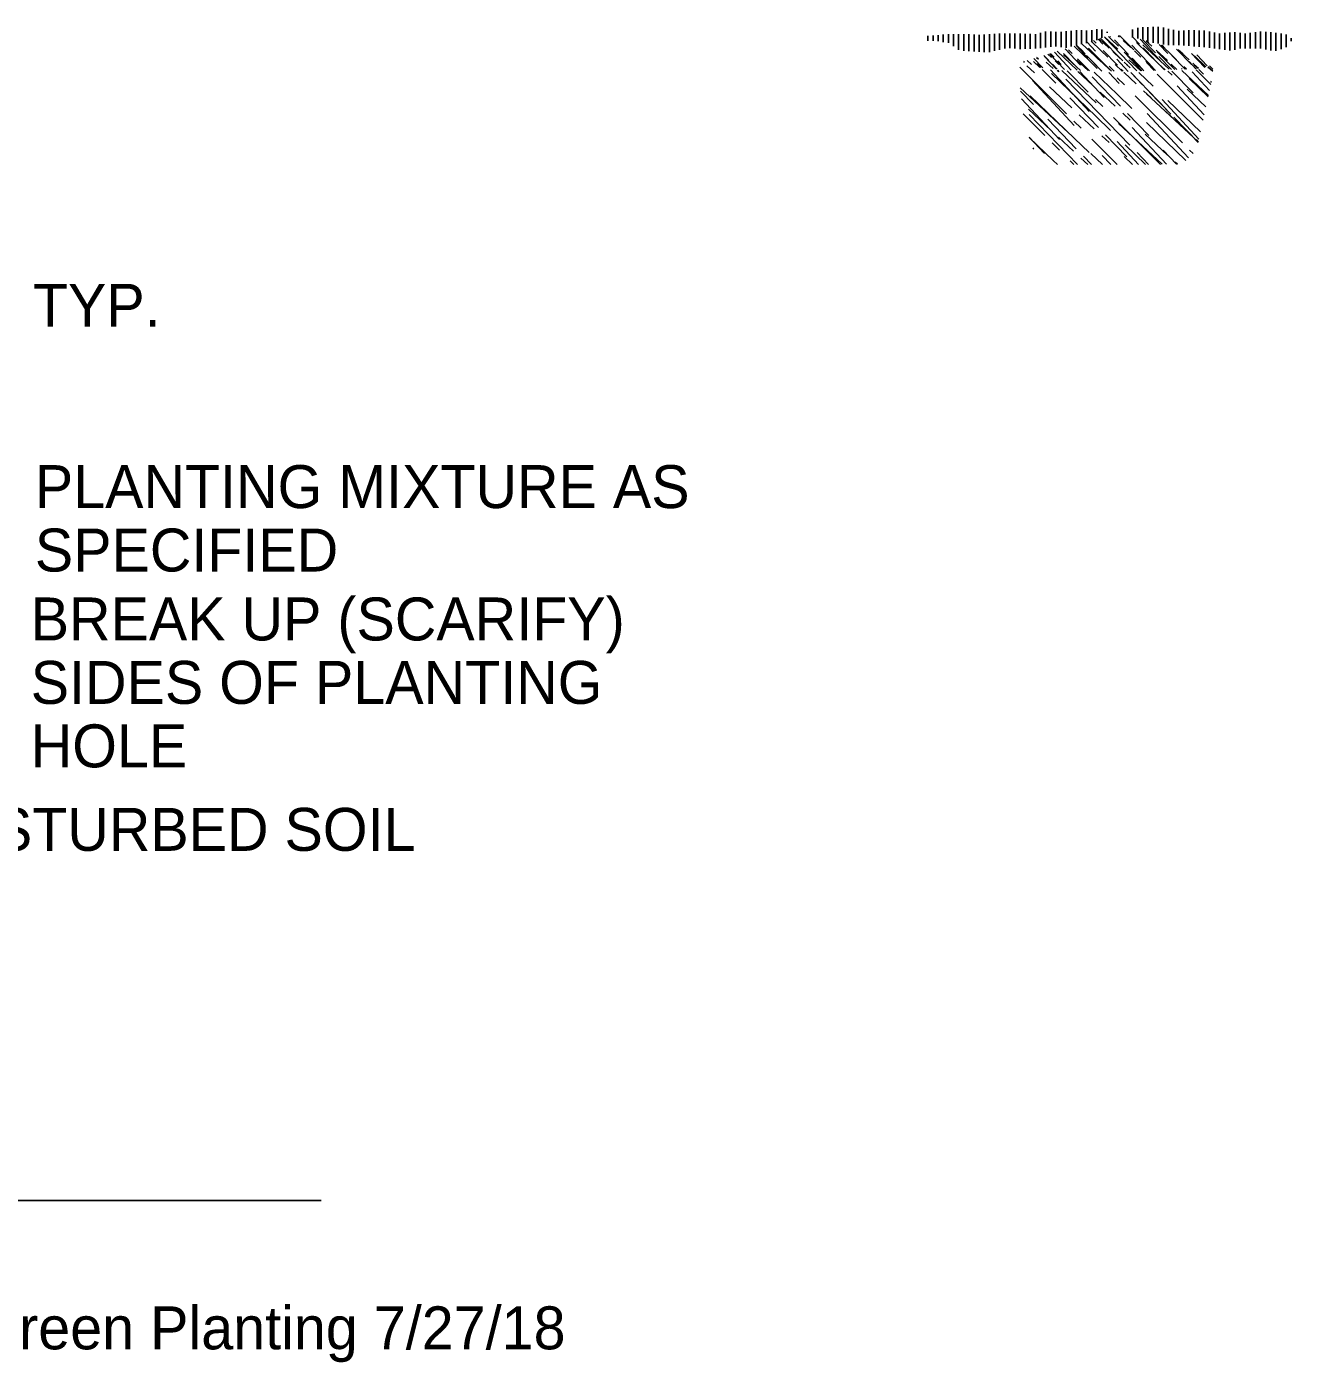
# Model space of a CAD drawing. Extents: x 10082 to 10257, y 10014 to 10069.
# Drawn here: x 10147.66 to 10168.25, y 10014.41 to 10036.16 of the extents above; entities that cross this region are included whole.
import ezdxf

# ---------------------------------------------------------------- set-up
doc = ezdxf.new("R2010")
doc.units = 0
for name, color, linetype in [('Default', 7, 'Continuous'), ('G-ANNO-CELL', 7, 'Continuous'), ('G-ANNO-TEXT', 7, 'Continuous'), ('G-DETL-TEXT', 7, 'Continuous')]:
    doc.layers.add(name, color=color, linetype=linetype)

# ---------------------------------------------------------------- blocks, each defined once
blk = doc.blocks.new('_X3')
at = {"layer": 'Default'}
for p, q in [((2.0243, 1.27594), (2.00019, 1.30005)), ((2.00379, 1.30073), (2.00766, 1.29713)), ((2.01867, 1.29176), (2.01176, 1.29892)), ((2.01595, 1.29868), (2.03605, 1.27712)), ((2.09892, 1.29113), (2.09126, 1.29879)), ((2.09277, 1.29887), (2.09513, 1.29644)), ((2.09741, 1.30026), (2.09986, 1.29797)), ((2.09986, 1.2991), (2.09818, 1.30084)), ((2.00665, 1.29312), (2.02831, 1.2699)), ((2.03941, 1.27469), (2.01657, 1.29675)), ((2.01961, 1.29846), (2.0203, 1.29775)), ((2.0396, 1.28172), (2.02178, 1.29833)), ((2.02398, 1.29394), (2.05706, 1.25968)), ((2.03552, 1.28717), (2.02452, 1.29817)), ((2.03015, 1.29786), (2.03784, 1.29069)), ((2.03121, 1.29782), (2.04379, 1.28434)), ((2.05215, 1.27995), (2.03745, 1.29517)), ((2.05044, 1.28611), (2.0386, 1.29755)), ((2.04621, 1.29726), (2.05153, 1.29156)), ((2.05423, 1.29091), (2.05049, 1.29465)), ((2.05403, 1.2972), (2.05396, 1.29726)), ((2.05407, 1.29726), (2.06028, 1.29147)), ((2.06357, 1.29098), (2.05744, 1.29733)), ((2.05749, 1.29733), (2.07609, 1.27806)), ((2.06908, 1.29018), (2.0616, 1.29741)), ((2.09486, 1.27273), (2.07107, 1.29652)), ((2.07661, 1.29795), (2.07884, 1.29587)), ((2.08969, 1.28678), (2.07879, 1.29807)), ((2.09766, 1.28545), (2.08382, 1.29836)), ((2.09752, 1.28479), (2.08772, 1.29425)), ((2.08918, 1.29773), (2.09823, 1.28803)), ((2.0988, 1.29263), (2.09916, 1.29226)), ((2.02516, 1.26624), (2.00034, 1.28938)), ((2.00726, 1.28073), (2.00053, 1.2877)), ((2.02839, 1.26327), (2.00555, 1.28533)), ((2.0154, 1.28991), (2.02701, 1.27908)), ((2.04171, 1.28708), (2.04945, 1.27986)), ((2.05805, 1.27876), (2.05044, 1.28611)), ((2.08417, 1.26098), (2.05985, 1.2853)), ((2.06415, 1.28787), (2.06802, 1.28426)), ((2.09237, 1.26144), (2.06564, 1.28637)), ((2.07827, 1.27575), (2.06725, 1.28717)), ((2.08144, 1.29051), (2.09547, 1.27547)), ((2.08658, 1.28865), (2.09636, 1.27953)), ((2.00097, 1.2837), (2.02057, 1.26268)), ((2.00457, 1.2783), (2.01619, 1.26747)), ((2.04073, 1.26892), (2.02603, 1.28415)), ((2.04301, 1.27969), (2.03927, 1.28343)), ((2.0737, 1.28329), (2.0927, 1.26292)), ((2.09351, 1.26659), (2.0767, 1.28283)), ((2.01307, 1.26472), (2.00182, 1.27597)), ((2.00495, 1.27556), (2.02992, 1.2497)), ((2.02931, 1.25789), (2.01461, 1.27312)), ((2.03178, 1.26846), (2.02804, 1.2722)), ((2.03088, 1.27547), (2.03862, 1.26825)), ((2.04703, 1.26734), (2.03941, 1.27469)), ((2.07286, 1.24983), (2.04862, 1.27407)), ((2.05332, 1.27626), (2.05719, 1.27265)), ((2.06685, 1.26472), (2.05583, 1.27614)), ((2.08597, 1.2518), (2.06567, 1.27141)), ((2.06596, 1.27608), (2.08736, 1.25313)), ((2.07576, 1.27704), (2.08737, 1.26621)), ((2.07977, 1.27425), (2.09233, 1.26125)), ((2.04249, 1.26465), (2.04636, 1.26104)), ((2.05543, 1.25369), (2.04441, 1.26511)), ((2.07378, 1.24984), (2.05121, 1.27089)), ((2.05822, 1.26886), (2.07596, 1.24984)), ((2.06493, 1.26543), (2.07654, 1.2546)), ((2.09232, 1.2612), (2.08562, 1.26814)), ((2.00496, 1.2639), (2.01283, 1.25547)), ((2.01736, 1.25186), (2.005, 1.26379)), ((2.00731, 1.25782), (2.00686, 1.25828)), ((2.02056, 1.25724), (2.01682, 1.26098)), ((2.02006, 1.26386), (2.0278, 1.25664)), ((2.036, 1.25592), (2.02839, 1.26327)), ((2.05048, 1.24976), (2.0374, 1.26285)), ((2.05048, 1.26164), (2.06153, 1.2498)), ((2.06518, 1.24981), (2.05464, 1.25999)), ((2.08973, 1.25541), (2.08791, 1.25724)), ((2.09124, 1.2626), (2.09239, 1.26153)), ((2.01962, 1.24967), (2.01736, 1.25186)), ((2.0281, 1.24969), (2.02617, 1.25162)), ((2.03167, 1.25304), (2.03522, 1.24972)), ((2.0372, 1.24972), (2.03299, 1.25409)), ((2.04285, 1.24974), (2.03677, 1.25541)), ((2.04274, 1.25442), (2.0471, 1.24975)), ((2.0541, 1.25382), (2.05842, 1.24979)), ((2.06074, 1.25587), (2.06659, 1.24981)), ((2.08121, 1.24986), (2.07421, 1.25711)), ((2.08041, 1.25099), (2.08162, 1.24986))]:
    blk.add_line(p, q, dxfattribs=at)
blk = doc.blocks.new('_X2')
at = {"layer": 'Default'}
for p, q in [((2.05846, 1.31543), (2.05846, 1.31955)), ((2.0611, 1.31488), (2.0611, 1.32049)), ((2.06375, 1.31432), (2.06375, 1.32074)), ((2.0664, 1.31344), (2.0664, 1.32083)), ((2.06904, 1.31275), (2.06904, 1.32091)), ((2.07169, 1.3123), (2.07169, 1.321)), ((2.07433, 1.31186), (2.07433, 1.32052)), ((2.07698, 1.31151), (2.07698, 1.31992)), ((2.07963, 1.31151), (2.07963, 1.31932)), ((2.08227, 1.31151), (2.08227, 1.31896)), ((2.08492, 1.31129), (2.08492, 1.31906)), ((2.08756, 1.31106), (2.08756, 1.31916)), ((2.09021, 1.31083), (2.09021, 1.31926)), ((2.09285, 1.3106), (2.09285, 1.31911)), ((2.0955, 1.31037), (2.0955, 1.31897)), ((2.09815, 1.31014), (2.09815, 1.31856)), ((2.10079, 1.30981), (2.10079, 1.318)), ((2.10344, 1.30946), (2.10344, 1.31754)), ((2.10608, 1.30912), (2.10608, 1.31782)), ((2.10873, 1.30878), (2.10873, 1.3181)), ((2.11138, 1.30911), (2.11138, 1.31811)), ((2.11402, 1.30969), (2.11402, 1.3178)), ((2.11667, 1.30976), (2.11667, 1.31753)), ((2.11931, 1.30976), (2.11931, 1.3179)), ((2.12196, 1.30976), (2.12196, 1.31827)), ((2.1246, 1.30969), (2.1246, 1.31857)), ((2.12725, 1.30919), (2.12725, 1.31841)), ((2.1299, 1.30869), (2.1299, 1.31825)), ((2.13254, 1.3086), (2.13254, 1.31784)), ((2.13519, 1.30938), (2.13519, 1.31743)), ((2.13783, 1.31035), (2.13783, 1.31702)), ((2.14048, 1.31352), (2.14048, 1.31514))]:
    blk.add_line(p, q, dxfattribs=at)
blk = doc.blocks.new('_X1')
at = {"layer": 'Default'}
for p, q in [((2.03994, 1.31413), (2.03994, 1.3197)), ((2.04258, 1.31531), (2.04258, 1.31953)), ((1.95263, 1.31367), (1.95263, 1.31626)), ((1.95527, 1.31367), (1.95527, 1.31649)), ((1.95792, 1.31347), (1.95792, 1.31671)), ((1.96056, 1.31305), (1.96056, 1.31693)), ((1.96321, 1.31262), (1.96321, 1.31716)), ((1.96585, 1.31087), (1.96585, 1.31717)), ((1.9685, 1.30902), (1.9685, 1.31717)), ((1.97115, 1.30856), (1.97115, 1.31717)), ((1.97379, 1.30841), (1.97379, 1.31709)), ((1.97644, 1.30823), (1.97644, 1.31698)), ((1.97908, 1.30803), (1.97908, 1.31687)), ((1.98173, 1.30783), (1.98173, 1.31697)), ((1.98438, 1.30782), (1.98438, 1.31715)), ((1.98702, 1.30847), (1.98702, 1.31734)), ((1.98967, 1.30912), (1.98967, 1.31751)), ((1.99231, 1.30978), (1.99231, 1.31751)), ((1.99496, 1.30997), (1.99496, 1.31751)), ((1.9976, 1.30972), (1.9976, 1.31751)), ((2.00025, 1.30947), (2.00025, 1.31744)), ((2.0029, 1.30951), (2.0029, 1.31735)), ((2.00554, 1.30962), (2.00554, 1.31726)), ((2.00819, 1.30972), (2.00819, 1.31721)), ((2.01083, 1.30997), (2.01083, 1.31787)), ((2.01348, 1.31029), (2.01348, 1.31853)), ((2.01613, 1.31062), (2.01613, 1.31847)), ((2.01877, 1.31073), (2.01877, 1.31833)), ((2.02142, 1.31041), (2.02142, 1.31836)), ((2.02406, 1.31013), (2.02406, 1.31864)), ((2.02671, 1.31079), (2.02671, 1.31892)), ((2.02935, 1.31146), (2.02935, 1.3192)), ((2.032, 1.31203), (2.032, 1.31914)), ((2.03465, 1.31248), (2.03465, 1.31899)), ((2.03729, 1.31294), (2.03729, 1.3192)), ((2.04523, 1.31784), (2.04523, 1.31835))]:
    blk.add_line(p, q, dxfattribs=at)
blk = doc.blocks.new('_X0')
at = {"layer": 'Default'}
for p, q in [((0.62626, 0.34419), (0.62488, 0.34553)), ((0.62556, 0.34559), (0.62589, 0.34524)), ((0.62998, 0.346), (0.63065, 0.34537)), ((0.63797, 0.33863), (0.63055, 0.34605)), ((0.60261, 0.33916), (0.61041, 0.33081)), ((0.6028, 0.33878), (0.60474, 0.33697)), ((0.60617, 0.33676), (0.6043, 0.33863)), ((0.61524, 0.33277), (0.60719, 0.34054)), ((0.60826, 0.34086), (0.61428, 0.33441)), ((0.61286, 0.33657), (0.60862, 0.34097)), ((0.60864, 0.34098), (0.61177, 0.33773)), ((0.62251, 0.3312), (0.6112, 0.34175)), ((0.61391, 0.34257), (0.61815, 0.33802)), ((0.61402, 0.33917), (0.61983, 0.33376)), ((0.62651, 0.32764), (0.61459, 0.33957)), ((0.62075, 0.33848), (0.6159, 0.34317)), ((0.61857, 0.34209), (0.61716, 0.34355)), ((0.61956, 0.34427), (0.62202, 0.34163)), ((0.62004, 0.34441), (0.62524, 0.33956)), ((0.63236, 0.33302), (0.62075, 0.34463)), ((0.62456, 0.3348), (0.62075, 0.33848)), ((0.62973, 0.33894), (0.62286, 0.34534)), ((0.62313, 0.34501), (0.63967, 0.32788)), ((0.63007, 0.34051), (0.62626, 0.34419)), ((0.63531, 0.33618), (0.62796, 0.34379)), ((0.63259, 0.34356), (0.63646, 0.33995)), ((0.63698, 0.34111), (0.6478, 0.3295)), ((0.64102, 0.34169), (0.63759, 0.34525)), ((0.65081, 0.33152), (0.63939, 0.34255)), ((0.64132, 0.34421), (0.65167, 0.33311)), ((0.64265, 0.34384), (0.64919, 0.33707)), ((0.6563, 0.32864), (0.64275, 0.34127)), ((0.64837, 0.33408), (0.64286, 0.33979)), ((0.64448, 0.34333), (0.64574, 0.34215)), ((0.64733, 0.3405), (0.64546, 0.34237)), ((0.64961, 0.33854), (0.65542, 0.33313)), ((0.6511, 0.34149), (0.65554, 0.33672)), ((0.65632, 0.33723), (0.65225, 0.34116)), ((0.65408, 0.33959), (0.65268, 0.34104)), ((0.66791, 0.33115), (0.66007, 0.33899)), ((0.66351, 0.33638), (0.661, 0.33873)), ((0.58147, 0.33228), (0.58106, 0.33267)), ((0.58512, 0.33102), (0.58297, 0.33324)), ((0.58617, 0.33258), (0.5894, 0.32957)), ((0.59106, 0.32942), (0.58625, 0.33423)), ((0.58872, 0.33377), (0.58774, 0.33468)), ((0.58797, 0.33159), (0.58989, 0.32953)), ((0.59409, 0.33316), (0.59152, 0.33582)), ((0.59184, 0.3352), (0.5978, 0.3288)), ((0.59636, 0.32894), (0.59279, 0.33238)), ((0.59365, 0.33646), (0.59545, 0.33478)), ((0.59439, 0.33668), (0.60226, 0.32854)), ((0.59681, 0.33489), (0.59487, 0.33683)), ((0.59697, 0.33746), (0.6056, 0.3282)), ((0.59739, 0.33297), (0.59932, 0.33117)), ((0.60866, 0.32809), (0.59848, 0.33792)), ((0.60055, 0.33115), (0.59868, 0.33302)), ((0.60715, 0.33106), (0.60164, 0.33677)), ((0.6104, 0.32802), (0.60175, 0.33609)), ((0.60861, 0.33336), (0.61441, 0.32795)), ((0.61508, 0.32785), (0.60897, 0.33395)), ((0.61361, 0.33582), (0.62147, 0.32769)), ((0.61904, 0.32909), (0.61524, 0.33277)), ((0.62144, 0.32769), (0.61654, 0.33277)), ((0.62176, 0.33195), (0.62563, 0.32834)), ((0.6296, 0.33067), (0.62225, 0.33828)), ((0.62717, 0.33776), (0.63104, 0.33415)), ((0.62924, 0.33389), (0.63515, 0.32755)), ((0.63298, 0.33234), (0.63491, 0.33054)), ((0.63311, 0.3375), (0.64219, 0.32776)), ((0.64323, 0.32781), (0.63388, 0.33684)), ((0.64174, 0.32774), (0.63553, 0.33353)), ((0.64266, 0.32857), (0.63715, 0.33428)), ((0.63839, 0.33815), (0.64033, 0.33634)), ((0.64171, 0.33489), (0.63984, 0.33676)), ((0.6442, 0.33274), (0.6492, 0.32807)), ((0.64856, 0.32804), (0.64452, 0.33208)), ((0.65931, 0.32852), (0.65013, 0.3377)), ((0.65102, 0.33517), (0.65753, 0.32844)), ((0.66013, 0.33355), (0.65632, 0.33723)), ((0.66465, 0.32865), (0.65776, 0.33579)), ((0.66277, 0.33713), (0.66664, 0.33352)), ((0.66663, 0.33259), (0.67015, 0.32881)), ((0.67082, 0.33369), (0.66778, 0.33684)), ((0.66781, 0.33683), (0.67477, 0.32962)), ((0.66857, 0.33171), (0.67051, 0.32991)), ((0.67528, 0.32996), (0.66945, 0.33559)), ((0.67065, 0.33604), (0.67592, 0.33038)), ((0.67476, 0.32961), (0.67266, 0.33179)), ((0.59835, 0.32875), (0.59593, 0.33125)), ((0.60341, 0.32829), (0.60336, 0.32834)), ((0.62537, 0.33028), (0.62784, 0.32762)), ((0.63204, 0.32758), (0.62836, 0.33113)), ((0.63259, 0.32758), (0.63144, 0.32876)), ((0.6361, 0.32928), (0.63423, 0.33115)), ((0.65416, 0.32829), (0.65081, 0.33152)), ((0.65397, 0.32828), (0.65205, 0.33027)), ((0.65735, 0.33132), (0.66031, 0.32856)), ((0.66276, 0.32898), (0.66307, 0.32865)), ((0.66521, 0.32865), (0.66394, 0.32988)), ((0.67149, 0.32894), (0.66932, 0.33097)), ((0.67024, 0.32882), (0.66978, 0.32928))]:
    blk.add_line(p, q, dxfattribs=at)
blk = doc.blocks.new('POINT_DISPLAY')
at = {"layer": 'Default'}
blk.add_line((0, 0), (0, 0), dxfattribs=at)

msp = doc.modelspace()

# ---------------------------------------------------------------- linework, layer by layer
at = {"layer": 'G-ANNO-TEXT'}
for p, q in [((10120.67, 10017.044), (10152.453, 10017.044)), ((10120.67, 10017.044), (10152.453, 10017.044)), ((10122.114, 10017.044), (10151.008, 10017.044)), ((10122.114, 10017.044), (10151.008, 10017.044))]:
    msp.add_line(p, q, dxfattribs=at)

# ---------------------------------------------------------------- block references
at = {"layer": 'Default', "xscale": 31.496062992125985, "yscale": 31.496062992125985}
for name, p in [('_X1', (10100.837, 9994.556)), ('_X0', (10145.594, 10025.119)), ('_X2', (10100.837, 9994.556)), ('_X3', (10100.837, 9994.556)), ('POINT_DISPLAY', (10166.894, 10035.483))]:
    msp.add_blockref(name, p, dxfattribs=at)

# ---------------------------------------------------------------- texts
at = {"layer": 'G-ANNO-CELL'}
msp.add_text('MD 329300 002 Evergreen Planting 7/27/18', height=0.7, dxfattribs=at).set_placement((10138.169, 10014.618))
at = {"layer": 'G-DETL-TEXT'}
for s, p in [('36" TYP.', (10146.127, 10031.274)), ('PLANTING MIXTURE AS ', (10147.792, 10028.321)), ('SPECIFIED', (10147.792, 10027.288)), ('BREAK UP (SCARIFY) ', (10147.725, 10026.165)), ('SIDES OF PLANTING ', (10147.725, 10025.132)), ('HOLE', (10147.725, 10024.098)), ('UNDISTURBED SOIL', (10144.837, 10022.738))]:
    msp.add_text(s, height=0.7, dxfattribs=at).set_placement(p)

doc.saveas('drawing.dxf')
